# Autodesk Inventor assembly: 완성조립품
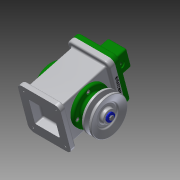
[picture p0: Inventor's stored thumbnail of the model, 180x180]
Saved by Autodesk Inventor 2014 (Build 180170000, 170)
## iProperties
Created: 2017-08
Part Number: 완성조립품
Document SubType Name: Assembly
Designer: user
Author: user
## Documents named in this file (18)
- C:\Users\user\Desktop\470808V1021\완성조립품.iam
- C:\Users\user\Desktop\470808V1021\본체.ipt
- C:\Users\user\Desktop\470808V1021\E-링.ipt
- C:\Users\user\Desktop\470808V1021\V-벨트풀리.ipt
- C:\Users\user\Desktop\470808V1021\덮개.ipt
- C:\Users\user\Desktop\470808V1021\뒤커버.ipt
- C:\Users\user\Desktop\470808V1021\링크.ipt
- C:\Users\user\Desktop\470808V1021\베어링 17 x 40 x 12.ipt
- C:\Users\user\Desktop\470808V1021\볼트 M4 x 8.ipt
- C:\Users\user\Desktop\470808V1021\볼트 M4 x 10.ipt
- C:\Users\user\Desktop\470808V1021\슬라이더.ipt
- C:\Users\user\Desktop\470808V1021\앞커버.ipt
- C:\Users\user\Desktop\470808V1021\오일 실 17 30 8.ipt
- C:\Users\user\Desktop\470808V1021\와셔 4x16.ipt
- C:\Users\user\Desktop\470808V1021\클레비스 핀 6 x 22.ipt
- 클레비스 핀 6 x 22.ipt
- C:\Users\user\Desktop\470808V1021\키 4 x 4 x 12.ipt
- C:\Users\user\Desktop\470808V1021\편심축.ipt
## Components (2 placed, 2 different names)
1. E-링:1 — Mate:45, Mate:46
2. V-벨트풀리:1 — Mate:4, Mate:5, Mate:6
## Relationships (5: Mate 5)
- Mate:4: V-벨트풀리:1
- Mate:5: V-벨트풀리:1
- Mate:6: V-벨트풀리:1
- Mate:45: E-링:1
- Mate:46: E-링:1
